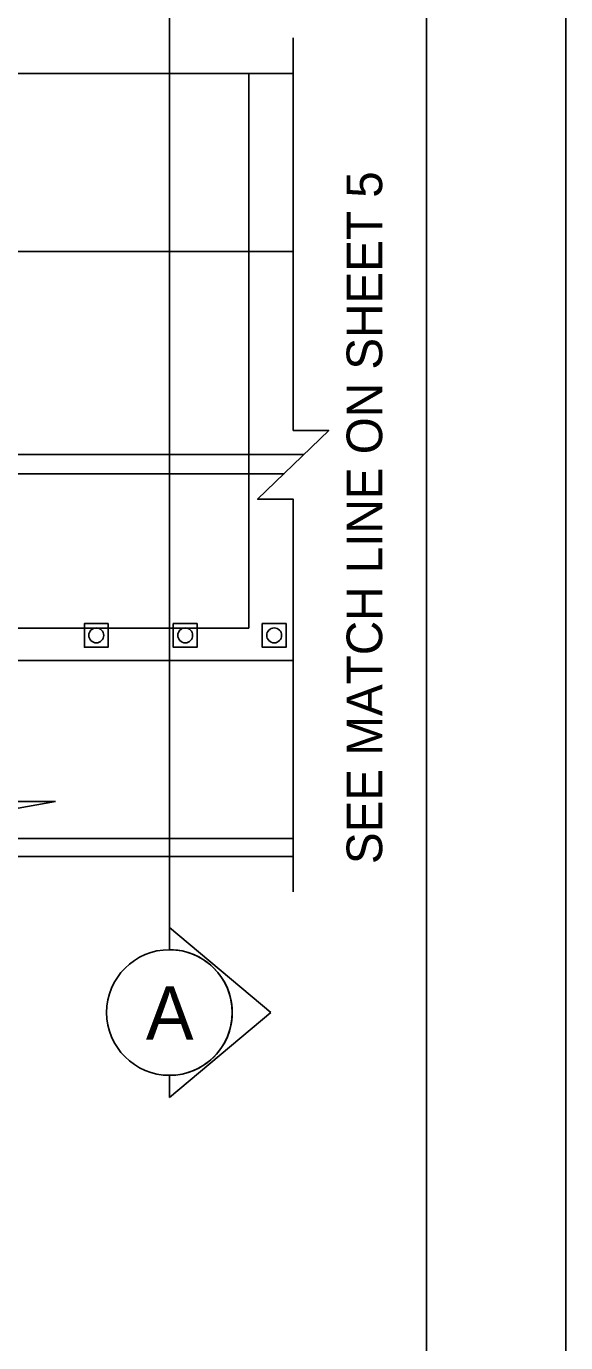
# Model space of a CAD drawing. Extents: x 99976 to 100136, y 99905 to 100011.
# Drawn here: x 100054.85 to 100056.062, y 99945.086 to 99948.045 of the extents above; entities that cross this region are included whole.
import ezdxf

# ---------------------------------------------------------------- set-up
doc = ezdxf.new("R2010")
doc.units = 0
for name, color, linetype in [('RD_ED_ShoulderPavedEdge', 7, 'Continuous'), ('RD_MK_LineEdgeWhite', 7, 'Continuous'), ('RD_MK_LineNoPass', 7, 'Continuous'), ('SH_GI_PlotLimits', 7, 'Continuous'), ('SH_GI_SheetBorder', 7, 'Continuous'), ('SH_TI_WZSectionCut', 7, 'Continuous'), ('TR_WZ_TrafficCone', 7, 'Continuous'), ('TR_WZ_WorkZoneDetails', 7, 'Continuous'), ('TR_WZ_WorkZoneTextCurrent', 7, 'Continuous')]:
    doc.layers.add(name, color=color, linetype=linetype)

msp = doc.modelspace()

# ---------------------------------------------------------------- linework, layer by layer
at = {"layer": 'RD_ED_ShoulderPavedEdge'}
for p, q in [((100040.1076, 99947.9393), (100055.45, 99947.9393)), ((100055.2197, 99947.9393), (100055.1196, 99947.9393)), ((100040.1076, 99946.1793), (100055.45, 99946.1793))]:
    msp.add_line(p, q, dxfattribs=at)
at = {"layer": 'RD_MK_LineEdgeWhite'}
for p, q in [((100053.0469, 99947.5393), (100055.45, 99947.5393)), ((100052.9246, 99946.6193), (100055.45, 99946.6193)), ((100052.1619, 99946.2193), (100055.45, 99946.2193))]:
    msp.add_line(p, q, dxfattribs=at)
at = {"layer": 'RD_MK_LineNoPass'}
for p, q in [((100053.0469, 99947.0826), (100055.4741, 99947.0826)), ((100053.0469, 99947.0393), (100055.4293, 99947.0393))]:
    msp.add_line(p, q, dxfattribs=at)
at = {"layer": 'SH_GI_PlotLimits'}
msp.add_lwpolyline([(100039.0625, 99939.6875), (100056.0625, 99939.6875), (100056.0625, 99950.6875), (100039.0625, 99950.6875)], close=True, dxfattribs=at)
at = {"layer": 'SH_GI_SheetBorder'}
msp.add_line((100055.75, 99950.375), (100055.75, 99940), dxfattribs=at)
at = {"layer": 'SH_TI_WZSectionCut'}
for p, q in [((100055.1718, 99948.0993), (100055.1718, 99946.0193)), ((100055.1718, 99946.0193), (100055.1718, 99945.9694)), ((100055.4, 99945.8282), (100055.1718, 99946.0193)), ((100055.1718, 99945.637), (100055.4, 99945.8282)), ((100055.1718, 99945.687), (100055.1718, 99945.637))]:
    msp.add_line(p, q, dxfattribs=at)
msp.add_circle((100055.1718, 99945.8282), 0.1412, dxfattribs=at)
msp.add_arc((100055.1718, 99945.8282), 0.1412, 269.9978, 90.0022, dxfattribs=at)
at = {"layer": 'TR_WZ_TrafficCone'}
for points in [[(100055.0339, 99946.7026), (100054.9805, 99946.7026), (100054.9805, 99946.6493), (100055.0339, 99946.6493), (100055.0339, 99946.7026)], [(100055.0339, 99946.6493), (100054.9805, 99946.6493), (100054.9805, 99946.7026), (100055.0339, 99946.7026), (100055.0339, 99946.6493)], [(100055.2339, 99946.7026), (100055.1805, 99946.7026), (100055.1805, 99946.6493), (100055.2339, 99946.6493), (100055.2339, 99946.7026)], [(100055.2339, 99946.6493), (100055.1805, 99946.6493), (100055.1805, 99946.7026), (100055.2339, 99946.7026), (100055.2339, 99946.6493)], [(100055.4339, 99946.7026), (100055.3805, 99946.7026), (100055.3805, 99946.6493), (100055.4339, 99946.6493), (100055.4339, 99946.7026)], [(100055.4339, 99946.6493), (100055.3805, 99946.6493), (100055.3805, 99946.7026), (100055.4339, 99946.7026), (100055.4339, 99946.6493)]]:
    msp.add_lwpolyline(points, dxfattribs=at)
for centre in [(100055.0072, 99946.676), (100055.2072, 99946.676), (100055.4072, 99946.676)]:
    msp.add_circle(centre, 0.0167, dxfattribs=at)
at = {"layer": 'TR_WZ_WorkZoneDetails'}
msp.add_lwpolyline([(100055.45, 99946.0993), (100055.45, 99946.9819), (100055.3699, 99946.9819), (100055.53, 99947.1367), (100055.45, 99947.1367), (100055.45, 99948.0193)], dxfattribs=at)
for points in [[(100055.35, 99946.6926), (100054.0546, 99946.6926), (100053.0469, 99946.6926), (100053.0469, 99947.0831), (100053.0469, 99947.0831), (100053.0469, 99947.0831), (100053.0469, 99947.3825), (100053.0469, 99947.3825), (100053.0469, 99947.3825), (100053.0469, 99947.6728), (100053.0469, 99947.9393), (100053.513, 99947.9393), (100054.3391, 99947.9393), (100055.35, 99947.9393), (100055.35, 99947.5174)], [(100054.9156, 99946.3026), (100054.6968, 99946.264), (100054.7191, 99946.3026)]]:
    msp.add_lwpolyline(points, close=True, dxfattribs=at)

# ---------------------------------------------------------------- texts
at = {"layer": 'SH_TI_WZSectionCut'}
msp.add_text('A', height=0.12, rotation=0.01, dxfattribs=at).set_placement((100055.1189, 99945.7673))
at = {"layer": 'TR_WZ_WorkZoneTextCurrent'}
msp.add_text('SEE MATCH LINE ON SHEET 5', height=0.08, rotation=90, dxfattribs=at).set_placement((100055.65, 99946.1618))

doc.saveas('drawing.dxf')
